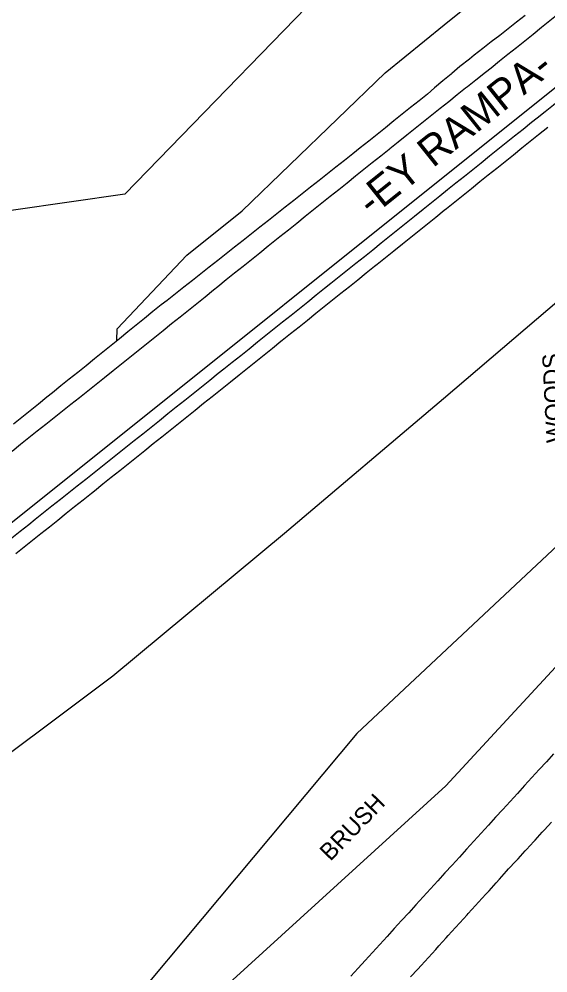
# Model space of a CAD drawing. Extents: x 1806071 to 1809844, y 912722 to 917035.
# Drawn here: x 1807969.6 to 1808092.6, y 914963.4 to 915185.1 of the extents above; entities that cross this region are included whole.
import ezdxf

# ---------------------------------------------------------------- set-up
doc = ezdxf.new("R2010")
doc.units = 0
for name, color, linetype in [('Exist Horizontal Alignment', 7, 'Continuous'), ('Exist Horizontal Alignment Direction Label', 7, 'Continuous'), ('Exist Right of Way Line', 7, 'Continuous'), ('Exist Roads EOP', 7, 'Continuous'), ('Exist Roads EOT', 7, 'Continuous'), ('Exist Roads Soil', 7, 'Continuous'), ('Exist Vegetation Hedge Row', 7, 'Continuous'), ('Exist Vegetation Hedge Row Text', 7, 'Continuous'), ('Exist Vegetation Woods Line', 7, 'Continuous'), ('Exist Vegetation Woods Line Text', 7, 'Continuous')]:
    doc.layers.add(name, color=color, linetype=linetype)

msp = doc.modelspace()

# ---------------------------------------------------------------- linework, layer by layer
at = {"layer": 'Exist Horizontal Alignment'}
msp.add_line((1808496.99, 915491.27), (1807817.19, 914947.49), dxfattribs=at)
at = {"layer": 'Exist Right of Way Line'}
msp.add_arc((1805206.16, 917989.46), 3373.5, 298.4006, 326.99746, dxfattribs=at)
at = {"layer": 'Exist Roads EOP'}
for points in [[(1808087.28, 915185.98), (1808085.32, 915184.44), (1808083.35, 915182.89), (1808081.39, 915181.34), (1808079.42, 915179.8), (1808077.46, 915178.25), (1808075.49, 915176.71), (1808074.34, 915175.8)], [(1808074.34, 915175.8), (1808072.16, 915174.07), (1808070.24, 915172.46), (1808070.09, 915172.35), (1808068.18, 915170.74), (1808066.27, 915169.13), (1808064.58, 915167.7), (1808062.63, 915166.14), (1808060.68, 915164.58), (1808058.73, 915163.01), (1808056.78, 915161.45), (1808054.83, 915159.88), (1808052.88, 915158.32), (1808050.93, 915156.75), (1808048.98, 915155.19), (1808047.23, 915153.79), (1808045.27, 915152.24), (1808043.3, 915150.69), (1808041.34, 915149.15), (1808039.38, 915147.6), (1808037.41, 915146.05), (1808035.45, 915144.5), (1808033.49, 915142.95), (1808031.52, 915141.41), (1808029.56, 915139.86), (1808027.6, 915138.31), (1808025.64, 915136.76), (1808023.67, 915135.21), (1808021.71, 915133.67), (1808019.75, 915132.12), (1808017.78, 915130.57), (1808015.82, 915129.02), (1808013.86, 915127.48), (1808011.89, 915125.93), (1808009.93, 915124.38), (1808007.97, 915122.83), (1808006, 915121.28), (1808004.04, 915119.74), (1808002.71, 915118.69), (1808000.77, 915117.12), (1807998.82, 915115.55), (1807996.88, 915113.97), (1807994.94, 915112.4), (1807992.99, 915110.83), (1807991.05, 915109.26), (1807989.1, 915107.69), (1807987.16, 915106.12), (1807985.21, 915104.55), (1807983.27, 915102.97), (1807981.32, 915101.4), (1807979.38, 915099.83), (1807977.44, 915098.26), (1807976.13, 915097.2), (1807974.18, 915095.64), (1807972.22, 915094.07), (1807970.27, 915092.51), (1807968.32, 915090.95)], [(1807968.87, 915060.88), (1807970.82, 915062.44), (1807972.78, 915064), (1807974.73, 915065.56), (1807976.69, 915067.12), (1807978.64, 915068.67), (1807980.6, 915070.23), (1807982.55, 915071.79), (1807984.51, 915073.35), (1807986.46, 915074.91), (1807987.19, 915075.49), (1807989.14, 915077.05), (1807991.09, 915078.61), (1807993.04, 915080.17), (1807994.99, 915081.74), (1807996.95, 915083.3), (1807998.9, 915084.86), (1808000.85, 915086.43), (1808002.8, 915087.99), (1808004.75, 915089.55), (1808006.7, 915091.11), (1808008.66, 915092.68), (1808010.61, 915094.24), (1808012.56, 915095.8), (1808014.51, 915097.36), (1808016.46, 915098.93), (1808016.88, 915099.26), (1808018.83, 915100.83), (1808020.78, 915102.39), (1808022.73, 915103.96), (1808024.67, 915105.53), (1808026.62, 915107.09), (1808028.57, 915108.66), (1808030.52, 915110.22), (1808030.83, 915110.47), (1808032.78, 915112.04), (1808034.73, 915113.6), (1808036.69, 915115.16), (1808038.64, 915116.72), (1808040.59, 915118.29), (1808042.54, 915119.85), (1808044.49, 915121.41), (1808046.44, 915122.97), (1808048.4, 915124.53), (1808050.35, 915126.1), (1808052.3, 915127.66), (1808052.92, 915128.15), (1808054.86, 915129.72), (1808056.81, 915131.28), (1808058.76, 915132.85), (1808060.71, 915134.42), (1808062.66, 915135.98), (1808064.61, 915137.55), (1808066.56, 915139.11), (1808068.51, 915140.68), (1808069, 915141.07), (1808070.94, 915142.64), (1808072.89, 915144.2), (1808074.84, 915145.77), (1808076.79, 915147.33), (1808078.74, 915148.9), (1808080.69, 915150.47), (1808082.64, 915152.03), (1808084.59, 915153.6), (1808086.54, 915155.16), (1808088.48, 915156.73), (1808090.43, 915158.3), (1808092.6, 915160.03)], [(1808093.92, 915014.34), (1808092.24, 915012.49), (1808090.55, 915010.64), (1808088.87, 915008.79), (1808087.18, 915006.95), (1808085.5, 915005.1), (1808083.82, 915003.25), (1808082.13, 915001.4), (1808080.45, 914999.56), (1808078.76, 914997.71), (1808077.08, 914995.86), (1808075.4, 914994.01), (1808073.71, 914992.17), (1808072.03, 914990.32), (1808070.34, 914988.47), (1808068.66, 914986.62), (1808066.98, 914984.77), (1808065.29, 914982.93), (1808063.61, 914981.08), (1808061.92, 914979.23), (1808060.24, 914977.38), (1808058.56, 914975.54), (1808056.87, 914973.69), (1808055.19, 914971.84), (1808053.5, 914969.99), (1808051.82, 914968.15), (1808050.14, 914966.3), (1808048.45, 914964.45), (1808046.77, 914962.6)]]:
    msp.add_lwpolyline(points, dxfattribs=at)
at = {"layer": 'Exist Roads EOT'}
for points in [[(1808095.02, 915186.27), (1808093.07, 915184.7), (1808091.12, 915183.14), (1808089.17, 915181.57), (1808087.22, 915180.01), (1808085.27, 915178.44), (1808083.32, 915176.88), (1808081.37, 915175.31), (1808079.42, 915173.75), (1808078.1, 915172.72)], [(1808090.07, 915162.18), (1808091.99, 915163.63), (1808093.93, 915165.21), (1808095.87, 915166.79), (1808097.08, 915167.78), (1808099.04, 915169.34), (1808101, 915170.9), (1808102.95, 915172.45), (1808104.91, 915174.01), (1808106.86, 915175.57), (1808108.82, 915177.12), (1808110.77, 915178.68), (1808112.73, 915180.24), (1808114.69, 915181.8), (1808116.64, 915183.35), (1808118.5, 915184.83), (1808120.45, 915186.4)], [(1808078.09, 915172.71), (1808075.85, 915170.95), (1808073.89, 915169.4), (1808073.44, 915169.04), (1808071.49, 915167.48), (1808069.53, 915165.92), (1808067.58, 915164.35), (1808065.63, 915162.79), (1808063.68, 915161.23), (1808061.72, 915159.67), (1808059.77, 915158.11), (1808057.82, 915156.55), (1808055.87, 915154.99), (1808055.67, 915154.83), (1808053.72, 915153.26), (1808051.77, 915151.7), (1808049.82, 915150.14), (1808047.86, 915148.57), (1808045.91, 915147.01), (1808043.96, 915145.45), (1808042.01, 915143.88), (1808040.06, 915142.32), (1808038.11, 915140.76), (1808036.16, 915139.2), (1808034.21, 915137.63), (1808032.26, 915136.07), (1808030.31, 915134.51), (1808028.35, 915132.94), (1808027.56, 915132.31), (1808025.61, 915130.74), (1808023.66, 915129.17), (1808021.72, 915127.6), (1808019.77, 915126.03), (1808017.82, 915124.47), (1808015.88, 915122.9), (1808014.86, 915122.08), (1808012.91, 915120.51), (1808010.96, 915118.94), (1808009.01, 915117.37), (1808007.07, 915115.81), (1808005.12, 915114.24), (1808003.17, 915112.67), (1808001.22, 915111.11), (1807999.27, 915109.54), (1807997.35, 915107.99), (1807995.4, 915106.44), (1807993.44, 915104.88), (1807991.49, 915103.32), (1807989.53, 915101.76), (1807987.58, 915100.21), (1807985.62, 915098.65), (1807983.67, 915097.09), (1807981.71, 915095.53), (1807979.75, 915093.98), (1807977.8, 915092.42), (1807975.84, 915090.86), (1807973.89, 915089.3), (1807971.93, 915087.75), (1807969.98, 915086.19), (1807968.02, 915084.63)], [(1807967.98, 915064.52), (1807969.93, 915066.08), (1807971.89, 915067.64), (1807973.39, 915068.83), (1807975.35, 915070.39), (1807977.3, 915071.94), (1807979.26, 915073.5), (1807981.22, 915075.05), (1807983.18, 915076.6), (1807985.13, 915078.16), (1807987.09, 915079.71), (1807989.05, 915081.27), (1807991.01, 915082.82), (1807992.53, 915084.04), (1807994.49, 915085.6), (1807996.44, 915087.16), (1807998.39, 915088.72), (1808000.34, 915090.28), (1808002.29, 915091.84), (1808004.25, 915093.41), (1808006.2, 915094.97), (1808008.15, 915096.53), (1808010.1, 915098.09), (1808012.06, 915099.65), (1808014.01, 915101.21), (1808015.96, 915102.78), (1808017.26, 915103.82), (1808019.21, 915105.38), (1808021.17, 915106.94), (1808023.12, 915108.5), (1808025.07, 915110.06), (1808027.02, 915111.62), (1808028.98, 915113.19), (1808030.93, 915114.75), (1808032.88, 915116.31), (1808034.83, 915117.87), (1808036.78, 915119.43), (1808038.74, 915120.99), (1808040.69, 915122.55), (1808042.12, 915123.7), (1808044.07, 915125.26), (1808046.02, 915126.83), (1808047.97, 915128.39), (1808049.92, 915129.95), (1808051.87, 915131.52), (1808053.82, 915133.08), (1808055.77, 915134.65), (1808057.72, 915136.21), (1808059.67, 915137.77), (1808061.62, 915139.34), (1808063.57, 915140.9), (1808065.52, 915142.47), (1808067.47, 915144.03), (1808069.27, 915145.48), (1808071.22, 915147.04), (1808073.17, 915148.61), (1808075.12, 915150.17), (1808077.07, 915151.74), (1808079.02, 915153.31), (1808080.97, 915154.87), (1808082.91, 915156.44), (1808084.86, 915158), (1808086.81, 915159.57), (1808088.76, 915161.14), (1808090.07, 915162.18)], [(1808060.64, 914962.44), (1808062.34, 914964.28), (1808063.12, 914965.12), (1808064.82, 914966.99), (1808066.51, 914968.84), (1808067.26, 914969.67), (1808068.93, 914971.53), (1808069.44, 914972.1), (1808071.11, 914973.95), (1808072.12, 914975.03), (1808073.79, 914976.89), (1808074.05, 914977.17), (1808075.73, 914979.03), (1808076.46, 914979.84), (1808078.17, 914981.67), (1808078.92, 914982.47), (1808080.58, 914984.34), (1808081.31, 914985.15), (1808082.97, 914987.02), (1808083.45, 914987.56), (1808085.16, 914989.39), (1808085.66, 914989.93), (1808087.35, 914991.77), (1808087.63, 914992.08), (1808089.33, 914993.92), (1808089.6, 914994.21), (1808091.28, 914996.07), (1808091.77, 914996.61), (1808093.47, 914998.45)]]:
    msp.add_lwpolyline(points, dxfattribs=at)
at = {"layer": 'Exist Roads Soil'}
msp.add_line((1807992.39, 915110.42), (1807992.48, 915113.14), dxfattribs=at)
msp.add_lwpolyline([(1807992.48, 915113.14), (1808008.68, 915130.24), (1808021.53, 915140.52), (1808054.75, 915172.62), (1808068.45, 915183.76), (1808083.11, 915195.62), (1808116.69, 915223.2), (1808153.79, 915252.14), (1808175.15, 915269.73), (1808213.01, 915295.24), (1808245.87, 915317.84)], dxfattribs=at)
at = {"layer": 'Exist Vegetation Hedge Row'}
msp.add_lwpolyline([(1808182.81, 915194.98), (1808219.38, 915225.05), (1808257.17, 915255.38), (1808289.14, 915283.6), (1808381.78, 915355.26), (1808385.36, 915351.44), (1808204.93, 915154.1), (1808068.87, 915006.91), (1807946.32, 914895.38)], dxfattribs=at)
at = {"layer": 'Exist Vegetation Woods Line'}
for points in [[(1808500.82, 915704.61), (1808491.21, 915625.56), (1808495.36, 915566.18), (1808486.21, 915543.62), (1808230.53, 915336.55), (1808200.13, 915312.12), (1808141.53, 915267.56), (1808103.92, 915240.43), (1808069.03, 915211.34), (1808049.63, 915201.52), (1807994.2, 915144.45), (1807942.37, 915137.01), (1807895.45, 915162.79), (1807892.83, 915181.85), (1807930.19, 915207.19), (1807959.19, 915218.2), (1807984.75, 915260.79), (1807978.92, 915284.25), (1807953.04, 915291.1), (1807936.72, 915324.51), (1807911.11, 915525.74), (1807909.65, 915561.81), (1807936.43, 915572.07)], [(1808182.81, 915194.98), (1808194.59, 915182.96), (1808123.23, 915089.31), (1808048.18, 915019.02), (1807959.95, 914913.66), (1807901.26, 914850.85), (1807887.11, 914855.83), (1807879.29, 914881.53), (1807880.44, 914923.49), (1807894.04, 914955.02), (1807915.84, 914974.97), (1807953.6, 915004.2), (1807991.45, 915032.47), (1808031.33, 915065.58), (1808068.31, 915096.93), (1808108.92, 915131.55), (1808145.7, 915163.42), (1808182.81, 915194.98)]]:
    msp.add_lwpolyline(points, dxfattribs=at)

# ---------------------------------------------------------------- texts
at = {"layer": 'Exist Horizontal Alignment Direction Label'}
msp.add_text('-EY RAMPA-', height=7, rotation=38.6563, dxfattribs=at).set_placement((1808051.63, 915139.03))
at = {"layer": 'Exist Vegetation Hedge Row Text'}
msp.add_text('BRUSH', height=4, rotation=45.8732, dxfattribs=at).set_placement((1808042.02, 914989.18))
at = {"layer": 'Exist Vegetation Woods Line Text'}
msp.add_text('WOODS', height=4, rotation=92.8422, dxfattribs=at).set_placement((1808096.28, 915086.72))

doc.saveas('drawing.dxf')
